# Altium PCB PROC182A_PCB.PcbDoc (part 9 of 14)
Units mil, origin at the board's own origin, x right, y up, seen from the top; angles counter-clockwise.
Board outline 3168.31 x 3700.79 mil, 8 copper layers (Top Layer, L2_GND1, L3_SIG1, L4_PWR1, L5_PWR2, L6_SIG2, L7_GND2, Bottom Layer), stack 58.1 mil thick; 580 components, 391 nets, 8314 pads, 4370 vias.
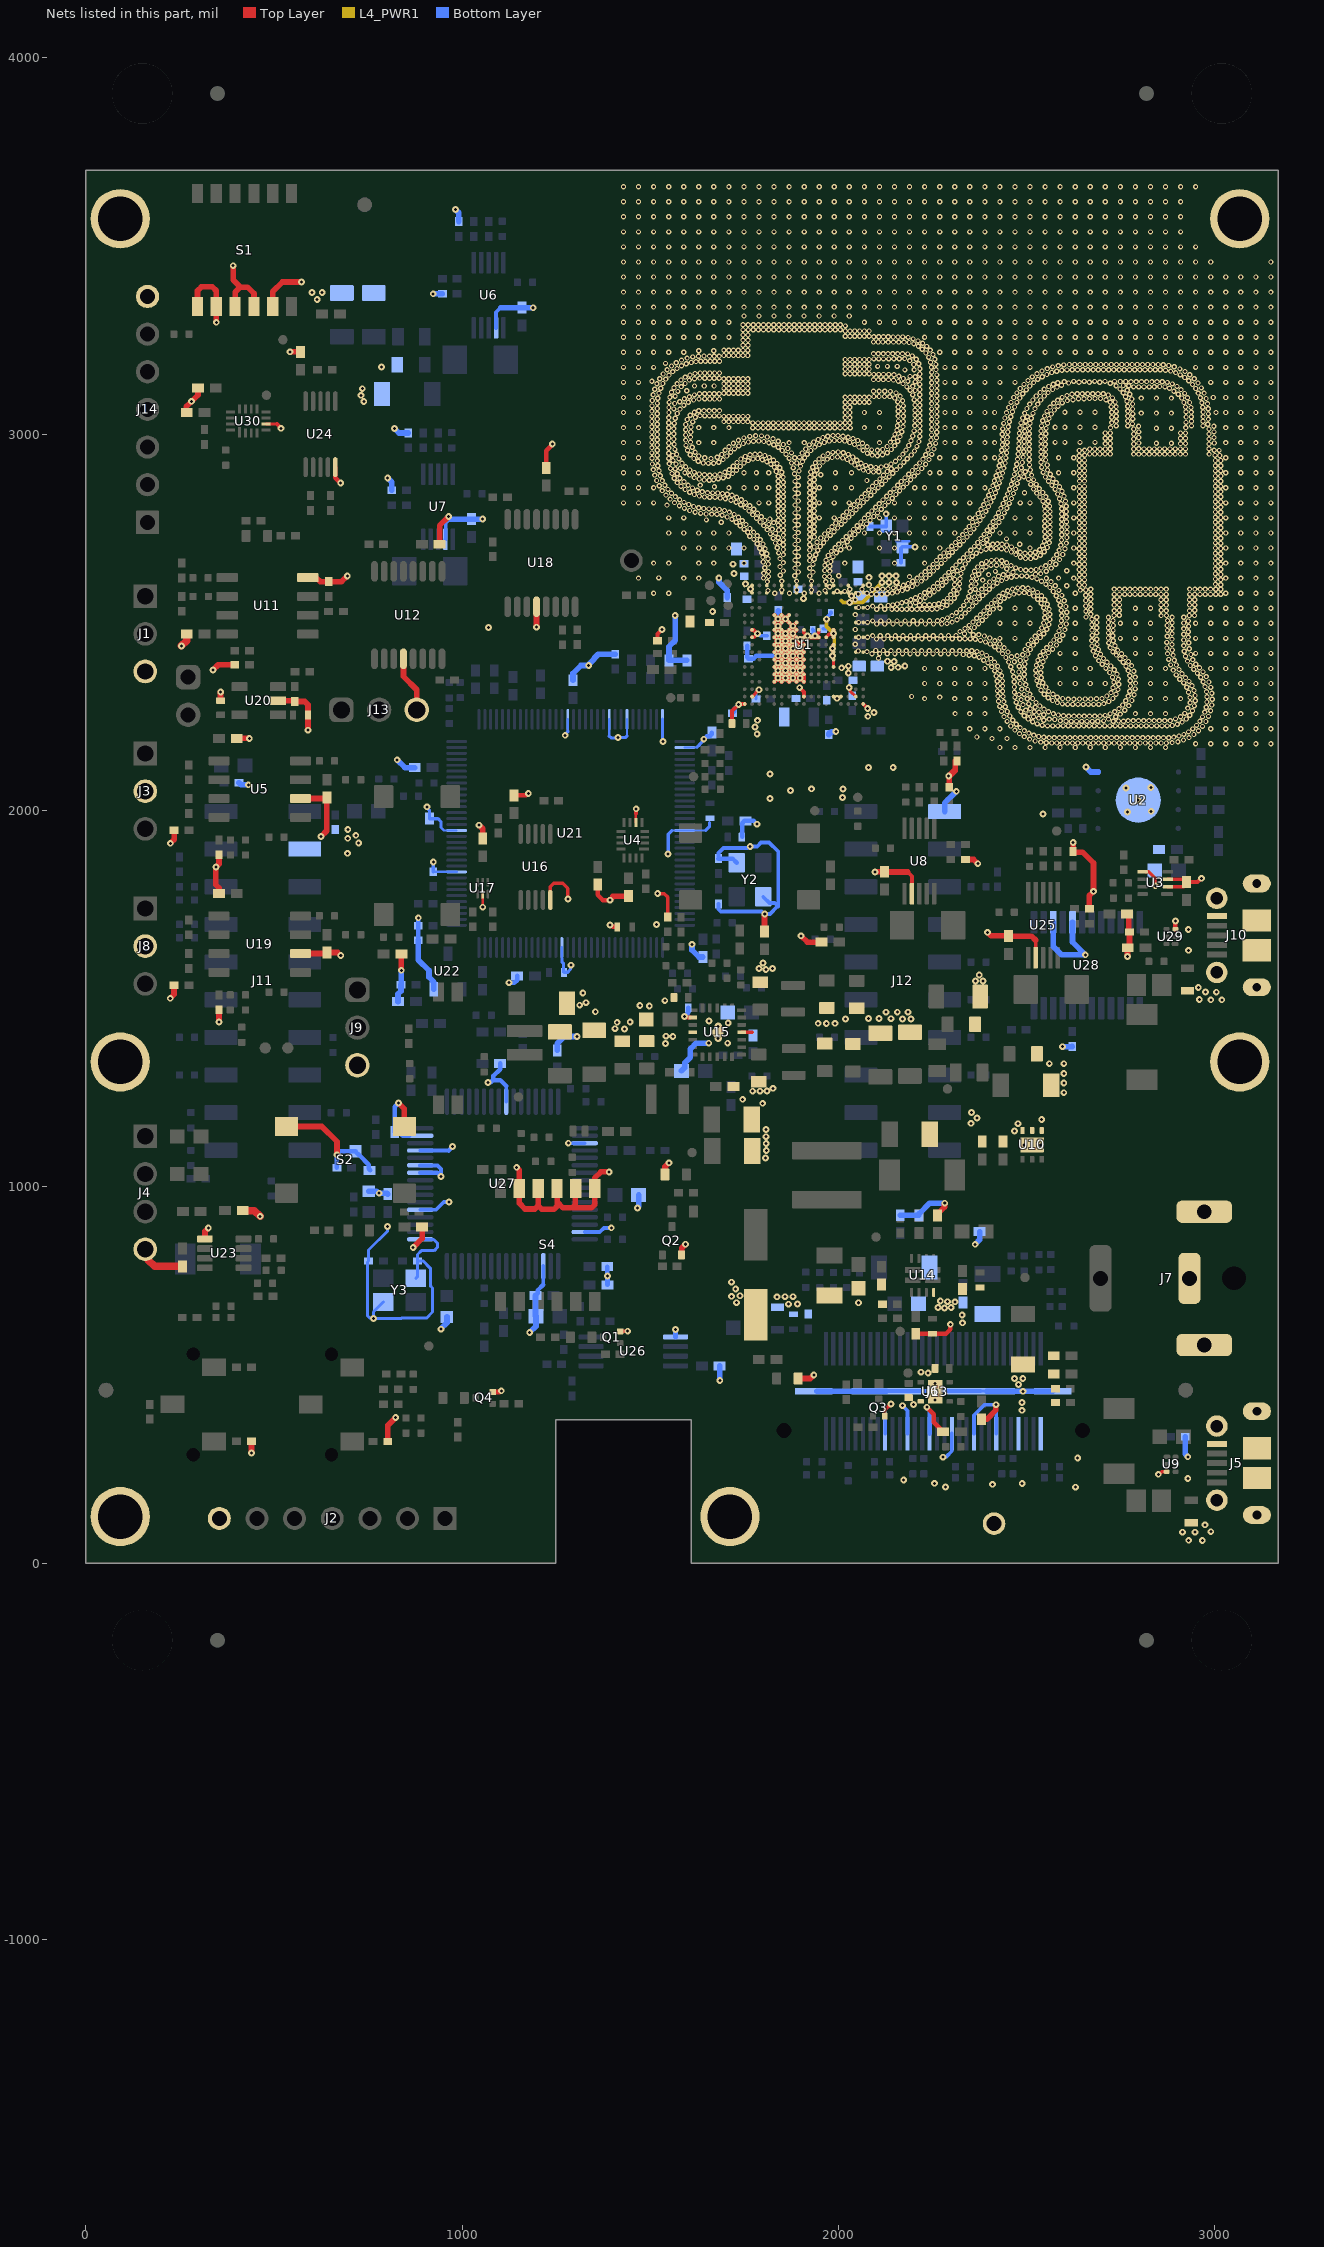
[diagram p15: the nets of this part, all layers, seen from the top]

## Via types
v1: diameter 13.77, hole 7, Top Layer to L2_GND1, tented both sides, 3444 vias
v2: diameter 18, hole 8, Top Layer to Bottom Layer, tented both sides, 911 vias
v3: diameter 13.77, hole 7, Top Layer to L2_GND1, tented top, 9 vias
v4: diameter 19.68, hole 7.87, Top Layer to Bottom Layer, 4 vias
v5: diameter 19.68, hole 7.87, Top Layer to Bottom Layer, tented both sides, 2 vias

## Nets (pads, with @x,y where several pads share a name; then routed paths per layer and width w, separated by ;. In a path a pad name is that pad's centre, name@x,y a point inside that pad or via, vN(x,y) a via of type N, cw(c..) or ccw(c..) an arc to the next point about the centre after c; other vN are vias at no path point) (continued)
GND: (continued)
  other v1: 2428.72,2167.48 2468.72,2167.48 2508.72,2167.48 2548.72,2167.48 2588.72,2167.48 2628.72,2167.48 2668.72,2167.48 2708.72,2167.48 2748.72,2167.48 2788.72,2167.48 2828.72,2167.48 2868.72,2167.48 2948.72,2177.48 2988.72,2177.48 3028.72,2177.48 3068.72,2177.48 3108.72,2177.48 3148.72,2177.48 2551.97,2180.12 2566.26,2179.62 2580.08,2179.62 2593.9,2179.62 2607.72,2179.62 2621.54,2179.62 2635.36,2179.62 2649.18,2179.62 2663,2179.62 2676.82,2179.62 2690.64,2179.62 2704.46,2179.62 2718.28,2179.62 2732.1,2179.62 2745.92,2179.62 2759.74,2179.62 2773.56,2179.62 2787.38,2179.62 2801.32,2179.62 2815.25,2179.62 2829.18,2179.62 2843.11,2179.64 2857.04,2179.64 2870.98,2179.64 2886.32,2180.47 2537.12,2181.81 2901.51,2182.99 2522.31,2184.91 2916.58,2187.38 2507.69,2189.76 2407.56,2191.44 2447.56,2191.44 2559.35,2193.71 2573.17,2193.71 2586.99,2193.71 2600.81,2193.71 2614.63,2193.71 2628.45,2193.71 2642.27,2193.71 2656.09,2193.71 2669.91,2193.71 2683.73,2193.71 2697.55,2193.71 2711.37,2193.71 2725.19,2193.71 2739.01,2193.71 2752.83,2193.71 2766.65,2193.71 2780.47,2193.71 2794.29,2193.71 2808.11,2193.71 2821.93,2193.71 2835.75,2193.71 2849.57,2193.71 2863.39,2193.71 2877.21,2193.68 2931.1,2193.82 2545.57,2194.68 2890.97,2195.03 2367.56,2195.44 2493.63,2196.46 2531.93,2196.91 2904.45,2198.05 2518.57,2200.44 2944.18,2202.11 2917.55,2202.48 2480.6,2204.52 2505.8,2205.73 2929.74,2208.99 2956.22,2212.02 2493.75,2212.5 2468.55,2213.85 2940.92,2217.1 2348.72,2217.48 2388.72,2217.48 2428.72,2217.48 2988.72,2217.48 3028.72,2217.48 3068.72,2217.48 3108.72,2217.48 3148.72,2217.48 2482.41,2220.4 2967.08,2223.62 2457.51,2224.73 2555.16,2224.97 2568.98,2224.96 2582.8,2224.96 2596.62,2224.96 2610.44,2224.96 2624.26,2224.96 2638.08,2224.96 2651.9,2224.96 2665.72,2224.96 2679.54,2224.96 2693.36,2224.96 2707.18,2224.96 2721,2224.96 2734.82,2224.96 2748.64,2224.96 2762.46,2224.96 2776.28,2224.96 2790.1,2224.96 2803.92,2224.96 2817.74,2224.96 2831.56,2224.96 2845.38,2224.96 2859.2,2224.96 2873.02,2224.96 2886.81,2225.83 2541.4,2226.33 2951.19,2226.35 2900.21,2229.22 2471.99,2229.48 2528.12,2230.15 2912.71,2235.1 2515.5,2235.78 2447.85,2236.85 2604.26,2237.28 2618.49,2236.86 2632.31,2236.86 2646.13,2236.86 2659.95,2236.86 2673.91,2236.86 2688.53,2237.05 2959.96,2237.03 2975.95,2236.43 2704.17,2238.27 2729.77,2237.36 2743.75,2237.92 2757.02,2237.38 2589.47,2238.82 2769.37,2239.05 2783.19,2239.05 2797.01,2239.05 2810.83,2239.05 2824.65,2239.05 2838.47,2239.05 2852.29,2239.05 2866.63,2238.91 2881.42,2238.98 2462.89,2239.88 2545.21,2239.76 2574.57,2241.85 2503.79,2243.11 2559.74,2242.87 2717.35,2242.9 2923.86,2243.27 2895.05,2243.54 2532.06,2245.61 2908.61,2249.22 2967.02,2248.91 2439.65,2249.68 2517.98,2249.41 2736.44,2249.35 2983.05,2250.21 2454.95,2251.19 2611.58,2250.95 2625.4,2250.95 2639.22,2250.95 2653.04,2250.95 2666.86,2250.95 2680.68,2250.95 2694.49,2251.23 2493.2,2251.99 2597.78,2251.78 2708.22,2252.8 2584.12,2253.86 2933.24,2253.42 2545.05,2254.39 2748.49,2256.16 2506.16,2256.88 2721.47,2256.75 2309.72,2257.48 2348.72,2257.48 2388.72,2257.48 2570.76,2257.4 2788.72,2257.48 2828.72,2257.48 2868.72,2257.48 2919.86,2258.14 3028.72,2257.48 3068.72,2257.48 3108.72,2257.48 3148.72,2257.48 2532.72,2261.08 2972.79,2261.47 2448.14,2263.21 2484.43,2262.68 2519.52,2262.48 2557.99,2262.69 2733.84,2262.91 2432.85,2263.42 2940.5,2265.18 2988.53,2265.13 2497.22,2266.98 2760.62,2266.55 2546.03,2269.61 2509.05,2270.9 2745.09,2270.93 2927.72,2272.18 2522.25,2274.29 2477.35,2274.55 2976.8,2274.7 2442.85,2275.98 2428.17,2276.72 2534.89,2277.79 2945.39,2278.11 2770.99,2278.75 2754.95,2280.61 2991.72,2280.48 2490.01,2281.53 2608.51,2282.19 2622.33,2282.19 2636.15,2282.19 2649.97,2282.19 2663.79,2282.19 2677.61,2282.19 2691.43,2282.14 2594.73,2283.29 2505.52,2283.38 2705.09,2284.24 2933.97,2286.27 2472,2287.29 2524.69,2287.12 2581.36,2286.77 2978.58,2288.4 2439.26,2289.33 2717.83,2289.57 2425.12,2290.48 2763.18,2291.72 2947.7,2291.73 2568.7,2292.31 2779.34,2292.56 2485,2294.84 2610.24,2296.08 2625.24,2295.94 2640.25,2296.28 2655.26,2296.28 2670.27,2296.28 2992.8,2295.83 2501.52,2297.08 2685.28,2297.09 2228.72,2297.48 2308.72,2297.48 2348.72,2297.48 2388.72,2297.48 2515.72,2297.63 2595.23,2297.61 2699.88,2297.73 2728.91,2297.83 2828.72,2297.48 2868.72,2297.48 2908.72,2297.48 3028.72,2297.48 3068.72,2297.48 3108.72,2297.48 3148.72,2297.48 2557.06,2299.78 2468.46,2300.65 2580.98,2300.99 2933.85,2300.42 2268.72,2301.48 2978.91,2302.22 2194.07,2303.05 2436.98,2302.96 2423.32,2303.98 2769.51,2304.01 2712.93,2304.33 2947.37,2305.55 2785.26,2307.63 2479.61,2308.45 2493.01,2308.64 2546.75,2308.97 2569.71,2309.19 2737.16,2308.92 2508.33,2309.31 2992.01,2311.72 2723.76,2313.47 2467.1,2314.4 2929.92,2314.36 2977.55,2315.97 2435.99,2316.74 2558.23,2316.68 2773.58,2317.21 2422.12,2317.88 2944.41,2319.04 2538,2319.67 2502.24,2321.71 2742.49,2321.67 2486.94,2322.71 2788.5,2323.22 2729.08,2326.46 2988.96,2327.19 2467.24,2328.22 2550.7,2328.13 2925.12,2327.57 2973.76,2329.26 2422.58,2330.9 2435.99,2330.56 2775.34,2330.92 2531.49,2331.86 2938.91,2331.72 2497.53,2334.71 2744.57,2335.34 2228.72,2337.48 2268.72,2337.48 2308.72,2337.48 2348.72,2337.48 2388.72,2337.48 2482.48,2337.44 2588.72,2337.48 2628.72,2337.48 2668.72,2337.48 2708.72,2337.48 2828.72,2337.48 2868.72,2337.48 3028.72,2337.48 3068.72,2337.48 3108.72,2337.48 3148.72,2337.48 2789.34,2338.67 2542.62,2339.68 2917.17,2339.31 2731.43,2340.79 2466.82,2342.03 2968.59,2342.08 2983.88,2341.71 2931.09,2343.12 2421.43,2343.78 2435.48,2344.37 2526.99,2344.93 2775.25,2344.74 2494.41,2348.17 2743.62,2349.12 2906.63,2348.89 2479.91,2352.83 2538.45,2352.96 2921.62,2353.18 2727.87,2354.26 2961.91,2354.18 2788.21,2354.44 2465.59,2355.8 2976.93,2355.92 2419.02,2357.58 2433.27,2358.01 2524.6,2358.54 2773.69,2358.47 2897.44,2360.36 2493.17,2361.93 2739.81,2362.41 2912.49,2363.56 2953.31,2364.99 2537.02,2366.59 2720.24,2366.89 2479.16,2368.26 2462.41,2369.25 2968.42,2368.54 2784.72,2370.3 2414.93,2371.13 2429.1,2371.19 2769.68,2371.7 2524.08,2372.35 2889.13,2373.12 2732.51,2374.14 2904.38,2374.75 2943.89,2375.1 2493.27,2375.75 2228.72,2377.48 2268.72,2377.48 2308.72,2377.48 2348.72,2377.48 2388.72,2377.48 2588.72,2377.48 2628.72,2377.48 2668.72,2377.48 2710.37,2377.81 2828.72,2377.48 2868.72,2377.48 2988.72,2377.48 3028.72,2377.48 3068.72,2377.48 3108.72,2377.48 3148.72,2377.48 2959.11,2379.35 2538.86,2381.04 2457.75,2382.26 2407,2382.44 2422.58,2383.38 2479.99,2383.45 2723.07,2384.24 2763.71,2383.51 2778.57,2385.17 2525.63,2386.08 2934.72,2385.45 2882.25,2386.94 2897.52,2386.75 2700.76,2388.73 2948.92,2388.78 2494.8,2389.49 2397.26,2392.34 2713.3,2394.01 2756.65,2393.75 2414.24,2394.39 2451.81,2394.74 2467.13,2395.25 2543.12,2395.48 2770.34,2395.94 2927.28,2397.09 2482.56,2398.63 2691.02,2398.37 2385.42,2399.43 2529.64,2399.31 2892.24,2399.52 2941.07,2401.09 2877.17,2401.74 2498.03,2402.93 2404.38,2404.07 2703.89,2404.13 2747.67,2403.38 2106.34,2404.56 2373.53,2406.98 2444.51,2406.47 2761.24,2406.39 2549.62,2407.99 2459.55,2408.84 2921.76,2409.76 2474.39,2411.22 2682.54,2411.09 2360.33,2411.38 2393.21,2412.22 2535.85,2411.66 2346.85,2412.74 2738.22,2412.88 2888.77,2412.89 2489.08,2414.18 2331.38,2414.6 2936.01,2414.61 2149.65,2416.28 2169.95,2416.28 2190.25,2416.28 2210.55,2416.28 2230.85,2416.28 2251.15,2416.28 2271.46,2416.28 2291.76,2416.28 2312.06,2416.28 2503.1,2415.78 2695.88,2415.4 2088.74,2416.56 2109.04,2416.81 2129.34,2416.47 2435.66,2417.08 2751.92,2416.43 2873.98,2416.94 2588.72,2417.48 2628.72,2417.48 2788.72,2417.48 2828.72,2417.48 2948.72,2417.48 2988.72,2417.48 3028.72,2417.48 3068.72,2417.48 3108.72,2417.48 3148.72,2417.48 2380.98,2418.66 2557.82,2419.68 2075.75,2422.25 2450.39,2421.36 2728.92,2422.08 2367.76,2422.67 2543.92,2422.88 2918.31,2423.15 2052.25,2423.95 2676.5,2423.62 2119.19,2425.22 2139.49,2424.94 2159.8,2424.9 2180.1,2424.9 2200.4,2424.9 2220.7,2424.9 2241,2424.9 2261.31,2424.9 2281.61,2424.9 2301.91,2424.9 2322.21,2424.9 2340.26,2425.02 2354.08,2424.63 2098.89,2425.39 2425.72,2426.68 2741.42,2426.38 2886.77,2426.57 2495.7,2427.91 2509.54,2428.01 2690.16,2427.98 2568.79,2428.39 2931.79,2430.01 2872.37,2432.04 2439.94,2432.49 2553.36,2432.97 2721.47,2432.95 2414.86,2435.23 2673.48,2437.23 2734.62,2438.08 2917.22,2438.21 2517.26,2439.47 2579.05,2439.74 2504.19,2441.27 2885.98,2441.06 2044.53,2441.72 2686.95,2441.42 2403.07,2442.45 2428.33,2442.5 2563.25,2442.62 2717.42,2445.48 2930.38,2445.78 2871.9,2446.87 2390.4,2447.95 2526.28,2449.94 2729.82,2451.08 2377.23,2452.15 2415.45,2451.31 2587.96,2452.23 2672.81,2451.55 2512.49,2453.13 2572.02,2453.3 2917.22,2453.27 2363.71,2455 2685.98,2455.21 2100.71,2455.89 2120.84,2456.06 2336.11,2456.26 2349.93,2456.09 2885.98,2455.55 2140.98,2456.34 2161.12,2456.38 2181.25,2456.38 2201.39,2456.38 2221.53,2456.38 2241.66,2456.38 2261.8,2456.38 2281.94,2456.38 2302.07,2456.38 2322.21,2456.38 2428.72,2457.48 2468.72,2457.48 2628.72,2457.48 2748.72,2457.48 2788.72,2457.48 2828.72,2457.48 2948.72,2457.48 2988.72,2457.48 3028.72,2457.48 3068.72,2457.48 3108.72,2457.48 3148.72,2457.48 2401.68,2458.38 2716.92,2458.48 2536.03,2459.74 2053.28,2460.58 2077.08,2460.59 2929.4,2460.85 2873.32,2463.28 2387.41,2463.66 2522.55,2463.42 2090.64,2464.72 2110.78,2464.47 2130.91,2464.81 2151.05,2464.5 2171.19,2464.5 2191.32,2464.5 2211.46,2464.5 2231.6,2464.5 2251.73,2464.5 2271.87,2464.5 2292.01,2465 2312.14,2465 2579.38,2465 2728.47,2464.63 2595.52,2465.96 2674.02,2465.48 2357.77,2466.9 2372.47,2467.49 2916.96,2468.33 2334.52,2469.88 2545.44,2469.86 2886.24,2470.04 2686.24,2472.08 2716.96,2472.08 2532.6,2473.05 2929.5,2475.16 2322.72,2475.88 2348.9,2477.88 2585.59,2477.34 2673.52,2479.28 2729.5,2478.55 2873.71,2478.55 2044.53,2481.09 2601.28,2480.68 2552.96,2481.45 2335.88,2483.58 2916.96,2483.39 2539.7,2485.09 2886.24,2484.53 2360.87,2486.3 2686.24,2485.89 2716.96,2485.89 2930.16,2489.47 2589.6,2490.57 2346.93,2491.88 2730.16,2491.73 2873.04,2491.73 2558.26,2494.22 2673.04,2493.69 2101.42,2495.54 2122.98,2495.54 2144.53,2495.54 2166.09,2495.54 2187.65,2495.54 2209.21,2495.54 2230.76,2495.54 2252.32,2495.54 2273.88,2495.54 2372.08,2496.02 2604.77,2495.58 2288.12,2496.98 2428.72,2497.48 2468.72,2497.48 2508.72,2497.48 2544.76,2498.28 2628.72,2497.48 2748.72,2497.48 2788.72,2497.48 2828.72,2497.48 2948.72,2497.48 2988.72,2497.48 3028.72,2497.48 3068.72,2497.48 3108.72,2497.48 3148.72,2497.48 2886.24,2499.02 2916.96,2498.45 2053.28,2499.95 2077.08,2499.96 2686.24,2499.7 2716.96,2499.7 2301.76,2500.7 2357.23,2501.1 2090.64,2503.84 2112.2,2503.84 2133.75,2503.84 2155.31,2503.84 2176.87,2503.84 2198.43,2504.05 2219.98,2503.8 2241.54,2504.12 2263.1,2504.16 2592.01,2504.18 2929.22,2503.77 2729.22,2504.9 2873.98,2504.9 2381.85,2505.79 2314.64,2506.73 2276.1,2507.75 2561.16,2507.73 2673.53,2508.1 2367,2510.87 2606.6,2511.19 2289.12,2511.83 2547.77,2512.18 2686.24,2513.51 2716.96,2513.51 2886.24,2513.51 2916.96,2513.51 2326.32,2514.78 2657.29,2514.4 2391.62,2515.57 2301.51,2517.86 2593.12,2517.95 2731.92,2518.08 2856.91,2517.94 2871.29,2518.08 2931.92,2518.08 2945.83,2518.05 2745.62,2519.02 2044.53,2520.46 2376.77,2520.64 2561.56,2521.54 2670.26,2521.81 2336.62,2524.48 2313.03,2525.5 2401.39,2525.34 2548.35,2525.56 2606.35,2526.99 2657.23,2529.46 2386.54,2530.42 2732.57,2531.23 2870.64,2531.23 2932.57,2531.23 2591.77,2531.7 2746.22,2532.33 2856.98,2532.33 2946.22,2532.33 2346.52,2534.08 2101.42,2534.91 2122.98,2534.91 2141.63,2534.91 2154.97,2534.91 2168.31,2534.91 2181.64,2534.91 2194.98,2534.91 2208.32,2534.91 2221.66,2534.91 2234.99,2534.91 2248.33,2534.91 2323.65,2534.35 2411.17,2535.11 2559.46,2535.2 2670.26,2535.12 2261.67,2536.38 2428.72,2537.48 2468.72,2537.48 2508.72,2537.48 2628.72,2537.48 2788.72,2537.48 2828.72,2537.48 2988.72,2537.48 3028.72,2537.48 3068.72,2537.48 3108.72,2537.48 3148.72,2537.48 2544.96,2538.75 2053.28,2539.32 2077.08,2539.33 2275,2539.55 2396.32,2540.19 2603.92,2542.08 2090.64,2543.21 2112.2,2543.21 2356.02,2543.58 2656.96,2543.42 2132.15,2544.81 2332.47,2544.98 2588.87,2545.22 2190.32,2546.08 2215.02,2545.68 2287.45,2545.56 2419.42,2546.28 2732.51,2546.2 2870.69,2546.2 2932.51,2546.2 2144.19,2546.52 2228.42,2546.68 2241.52,2546.98 2254.12,2547.28 2746.38,2546.36 2856.83,2546.36 2946.38,2546.36 2554.92,2548.26 2156.22,2548.88 2266.22,2549.28 2670.26,2548.44 2406.09,2549.96 2538.14,2550.78 2168.25,2551.89 2204.62,2551.88 2365.08,2552.99 2298.55,2553.79 2278.62,2555.18 2180.28,2555.63 2429.5,2555.8 2339.99,2556.58 2352.08,2556.74 2599.7,2557.24 2217.19,2557.9 2656.58,2557.92 2584.66,2558.38 2044.53,2559.83 2192.31,2560.07 2415.86,2559.73 2548.1,2560.28 2732.57,2560.12 2746.37,2560.12 2856.83,2560.12 2870.64,2560.12 2932.57,2560.12 2946.37,2560.12 2374.32,2562.25 2529.4,2561.35 2670.26,2561.75 2289.1,2563.6 2307.89,2563.98 2440.54,2564.09 2204.34,2565.16 2230.02,2564.98 2361.32,2567.38 2346.16,2568.94 2425.95,2569.18 2518.72,2569.88 2383.37,2571.22 2452.72,2570.58 2539.22,2570.87 2578.2,2570.59 2216.77,2571.37 2593.48,2571.74 2656.63,2571.93 2242.32,2572.86 2100.99,2574.23 2298.12,2573.7 2732.57,2574.29 2746.37,2574.29 2760.17,2574.29 2773.97,2574.29 2787.77,2574.29 2801.58,2574.29 2815.38,2574.29 2829.18,2574.29 2842.98,2574.29 2856.78,2574.29 2870.59,2574.29 2087.77,2574.34 2115.15,2574.41 2465.96,2575.11 2670.26,2575.06 2932.6,2574.39 2946.51,2574.39 2960.42,2574.39 2974.32,2574.39 2988.23,2574.39 3002.14,2574.39 3015.24,2574.39 2052.25,2575.44 2129.19,2575.79 2315.05,2575.8 1830.42,2577.09 1869.79,2577.09 1909.16,2577.09 1948.53,2577.09 2075.75,2577.14 2371.65,2576.86 2506.67,2576.76 1508.72,2577.48 1548.72,2577.48 2142.62,2577.79 2437.08,2577.38 2479.47,2578.27 2628.72,2577.48 3028.72,2577.48 3068.72,2577.48 3108.72,2577.48 3148.72,2577.48 2229,2578.47 2493.22,2578.98 2391.82,2579.88 2528.54,2579.63 2156.22,2580.78 2253.92,2580.88 2016.23,2582.24 2350.17,2582.17 2570.43,2582.02 1996.58,2582.46 2449.25,2583.92 1812.64,2584.82 1964.13,2584.82 2169.63,2584.61 2585.51,2584.82 1849.27,2585.85 1888.64,2585.85 1928.01,2585.85 2305.88,2585.75 2516.38,2586.2 2642.52,2585.78 2656.63,2585.83 2089.42,2587.3 2240.93,2586.34 2029.75,2588.06 2062.26,2587.8 2103.47,2588.2 2363.14,2587.7 2400.85,2588.11 2732.57,2588.28 2746.37,2588.28 2760.18,2588.28 2773.98,2588.28 2787.79,2588.28 2801.59,2588.28 2815.4,2588.28 2829.2,2588.28 2843.01,2588.28 2856.81,2588.28 2870.62,2588.28 2932.73,2588.23 2946.62,2588.23 2960.5,2588.23 2974.39,2588.23 2988.27,2588.23 3002.16,2588.14 3015.24,2588.14 2117.52,2588.4 2265.23,2588.99 2319.73,2588.8 2380.26,2588.42 2462.22,2588.67 2670.26,2588.37 2131.57,2589.55 2182.76,2589.45 2503.24,2590.48 2145.62,2591.58 2475.74,2591.55 2489.54,2592.3 2159.85,2592.64 2561.5,2592.57 1976.5,2594.83 2252.26,2594.67 2195.92,2595.38 2352.3,2595.82 2410.61,2596.7 2575.87,2597.25 2606.54,2597.29 2275.58,2598.21 2390.79,2597.86 2172.24,2598.43 2308.24,2599.79 2639.58,2599.35 2653.59,2599.35 3015.24,2599.8 2208.74,2602.01 2364.92,2601.78 2550.91,2601.45 3001.17,2601.65 2321.75,2602.47 2184.95,2603.37 2262.95,2603.79 2421.2,2604.07 2285.93,2607.66 2401.47,2607.39 2564.63,2608.27 1810.94,2608.32 1965.83,2608.32 2539.4,2609.11 1849.29,2609.65 1888.66,2609.65 1928.03,2609.65 2197.06,2609.43 2220.22,2609.51 2353.36,2609.6 1984.22,2610.65 2433.22,2610.89 2273.17,2613.18 2383.01,2612.35 2639.73,2612.76 2653.59,2612.76 2308.98,2613.89 3015.24,2613.56 2322.81,2616.25 2366.92,2615.38 2412.85,2615.59 2445.99,2616.18 2527.13,2615.46 3001.17,2615.33 1468.72,2617.48 1522.55,2618.24 1588.72,2617.48 1628.72,2617.48 1800.74,2617.79 2208.86,2617.5 2231.72,2617.78 2295.42,2617.6 2552.3,2617.4 2584.72,2617.48 2624.72,2617.48 3028.72,2617.48 3068.72,2617.48 3108.72,2617.48 3148.72,2617.48 2459.29,2619.91 2513.97,2619.67 1814.07,2621.77 1962.56,2621.82 1975.96,2621.91 2188.72,2621.48 1923.37,2623.18 2282.87,2623.03 2355.86,2623.19 2425.13,2622.55 2472.87,2622.47 2500.43,2622.44 1883.85,2623.66 2000.7,2623.92 2486.65,2623.56 1845.06,2625.1 2219.96,2625.87 2242.42,2626.88 2305.32,2627.18 2398.84,2626.96 2437.43,2626.74 2639.88,2626.57 2653.59,2626.57 2372.52,2627.98 2523.27,2628.26 3015.24,2627.32 2450.17,2628.8 3001.17,2629 2325.42,2629.82 2536.84,2629.43 1801.14,2630.88 2292.64,2632.8 2463.67,2632.96 1893.02,2633.71 1932.28,2633.48 1814.12,2635.18 2230.62,2634.78 1976.82,2636.08 2361.38,2635.87 2416.64,2635.48 2551.62,2635.7 1853.38,2636.53 2252.43,2636.53 2315.12,2636.98 2606.54,2637.29 1963.07,2637.8 2380.82,2638.88 2497.41,2638.45 2511.22,2638.38 2483.74,2640.54 2524.91,2640.34 2639.72,2640.38 2653.59,2640.38 3015.24,2641.07 2302.41,2642.57 2329.92,2642.89 2447.07,2642.38 3001.17,2642.68 1884.33,2644.19 1923.16,2643.78 2565.07,2644.2 1803.92,2644.88 2241.15,2644.44 2470.58,2644.75 2538.09,2644.48 2262.68,2646.62 2369.61,2646.96 1844.66,2648.14 2391.62,2647.78 1977.02,2649.28 2434.1,2649.48 2405.02,2651.28 2458.32,2651.14 2550.38,2650.81 1963.67,2651.61 2419.56,2651.63 2312.18,2652.34 1932.28,2654.08 2251.34,2654.12 2639.72,2654.19 2653.59,2654.19 1813.58,2655.15 1893.02,2654.66 2336.43,2655.08 2577.02,2654.6 3015.24,2654.83 2380.28,2655.75 2272.72,2656.61 3001.17,2656.35 1508.72,2657.48 1548.72,2657.48 1628.72,2657.48 1668.72,2657.48 1748.72,2657.48 2016.32,2657.48 2148.72,2657.48 2228.72,2657.48 2624.72,2657.48 3028.72,2657.48 3068.72,2657.48 3108.72,2657.48 3148.72,2657.48 1853.38,2658.66 2446.56,2658.38 2561.52,2658.98 1800.2,2660.42 1979.72,2661.73 2321.96,2662.12 2392.76,2661.69 2433.72,2663.51 1884.33,2665.14 1923.16,2664.38 1966.77,2665.07 2260.29,2664.56 2406.26,2664.66 2345,2665.92 2420.05,2665.51 2282.71,2666.76 2587.38,2666.73 1935.51,2667.88 2639.83,2668 2653.59,2668 1812.49,2668.93 2571.35,2668.7 3015.24,2668.59 1844.66,2669.32 2496.61,2669.73 2510.43,2669.51 3001.17,2670.03 2331.73,2671.89 2483.22,2673.15 2523.92,2672.49 1799.12,2673.38 1985.32,2673.88 2270.06,2674.33 1893.02,2675.61 2355.01,2675.45 2292.6,2676.85 1923.33,2677.91 1972.69,2677.56 2536.35,2678.53 1853.54,2679.9 1939.4,2679.83 2471.17,2679.92 2579.65,2679.75 2595.8,2680.46 2341.5,2681.66 2639.58,2681.81 2653.59,2681.81 1809.36,2682.39 2509.18,2683.22 3015.24,2682.35 2279.83,2684.11 2366.26,2683.47 2495.5,2683.61 3001.17,2683.7 1796.1,2684.81 1840.82,2684.68 1994.22,2685.01 1884.33,2686.09 2522.62,2686.18 2302.44,2686.38 2459.2,2686.83 2482.52,2686.58 2546.74,2687.65 1981.14,2688.5 2378.55,2689.8 1944.69,2691.26 1923.7,2692.25 2351.32,2691.68 2446.43,2692.1 2586.05,2691.99 2005.82,2693.14 2290.92,2692.55 2534.24,2692.85 1853.54,2693.48 2391.77,2693.84 2471.14,2693.67 1804.92,2695.47 2405.45,2695.78 2433.02,2695.44 2601.83,2695.35 2639.75,2695.62 2653.59,2695.62 3015.24,2696.1 1790.81,2696.67 1893.02,2696.56 2311.92,2696.48 2419.25,2696.58 1588.72,2697.48 1628.72,2697.48 1668.72,2697.48 1708.72,2697.48 1748.72,2697.48 1837.12,2698.08 1990.97,2698.22 2028.72,2697.48 2108.72,2697.48 2148.72,2697.48 2228.72,2697.48 2268.72,2697.48 2508.72,2697.48 2624.72,2697.48 3001.17,2697.38 3028.72,2697.48 3068.72,2697.48 3108.72,2697.48 3148.72,2697.48 2554.7,2698.95 1935.1,2700.09 2372.79,2700.53 2459.42,2700.48 1951.65,2701.65 2300.51,2702.21 2360.83,2701.9 2015.59,2702.91 2541.97,2703.71 2590.27,2705.16 1853.36,2706.24 1923.7,2706.07 2322.28,2706.27 2396.62,2706.28 2446.7,2705.48 1884.33,2707.04 1799.19,2708.05 2000.74,2707.99 2409.74,2707.98 2434.28,2707.88 2481.28,2707.32 1783.92,2708.68 2421.96,2709.1 2383.91,2709.77 2639.94,2709.43 2653.59,2709.43 3015.24,2709.86 1832.22,2710.68 2605.33,2710.57 3001.17,2711.05 1843.08,2712.27 1960.35,2711.73 2310.75,2712.23 2559.83,2711.78 1942.67,2712.66 2369.95,2712.32 2023.32,2713.88 2546.91,2715.16 2331.96,2716.41 1893.02,2717.51 2010.51,2717.76 1853.54,2719.01 2592.39,2718.81 1791.97,2719.84 1923.7,2719.89 2393.82,2719.66 1775.04,2720.49 1968.29,2721.43 2446.39,2721.69 1826.12,2722.98 2033.42,2723.28 2320.12,2722.77 2378.44,2722.76 2639.8,2723.24 2653.59,2723.24 1952.98,2724.27 3015.24,2723.62 1839.97,2725 3001.17,2724.72 2561.84,2725.45 2606.79,2725.39 1935.59,2726.8 2341.34,2726.91 1884.33,2727.99 2020.28,2727.53 2549.11,2727.35 1764.26,2728.98 1784.05,2730.38 1978.07,2731.13 1853.54,2731.77 2400.93,2731.69 2043.32,2733.28 2329.55,2733.17 2593.03,2732.62 1923.7,2733.71 2386.85,2733.72 1819.02,2735.08 1963.2,2734.57 1832.46,2736.26 2640.04,2737.05 2653.59,2737.05 1548.72,2737.48 1588.72,2737.48 1628.72,2737.48 1668.72,2737.48 1708.72,2737.48 2030.05,2737.3 2068.72,2737.48 2108.72,2737.48 2148.72,2737.48 2188.72,2737.48 2228.72,2737.48 2268.72,2737.48 2308.72,2737.48 2350.47,2737.72 2428.72,2737.48 2468.72,2737.48 2508.72,2737.48 2624.72,2737.48 3015.24,2737.38 3028.72,2737.48 3068.72,2737.48 3108.72,2737.48 3148.72,2737.48 1893.02,2738.46 2561.79,2739.27 3001.17,2738.4 1758.5,2739.4 1774.48,2739.68 2607.12,2739.53 1935.59,2740.62 1987.84,2740.83 2547.92,2741.38 2409.44,2743.24 2053.02,2743.38 2338.77,2743.64 1853.54,2744.53 1972.99,2744.35 2395.26,2744.69 1810.52,2746.28 1841.22,2745.48 1749.29,2747.1 2039.83,2747.08 2593.03,2746.44 1824.12,2747.68 1923.7,2747.53 1884.33,2748.94 2359.49,2748.43 1764.47,2749.51 1997.61,2750.54 2639.91,2750.86 2653.59,2750.86 3015.24,2751.13 3001.17,2752.07 2063.22,2752.98 2561.79,2753.09 1982.76,2754.13 2607.12,2753.42 1935.59,2754.44 2347.32,2754.55 2417.37,2755.28 2547.92,2755.23 2403.17,2756.02 1739.02,2756.64 1801.5,2756.99 1853.54,2757.29 2049.6,2756.85 1840.22,2758.18 1754.17,2760.11 1815.02,2760.18 1893.02,2759.41 2007.38,2760.24 2368.01,2759.69 2593.03,2760.26 1923.7,2761.35 2074.22,2761.54 1992.53,2763.9 1828,2764.91 2639.82,2764.67 2653.59,2764.67 3015.24,2764.89 1728.44,2766.11 2355.8,2765.68 2426.32,2766.14 3001.17,2765.75 1791.72,2766.76 2059.37,2766.62 2561.79,2766.91 2605.52,2767.08 1935.59,2768.26 2410.6,2767.68 2547.92,2769.05 1744.4,2769.88 1853.54,2770.06 1884.33,2769.89 2017.16,2769.94 1804.42,2770.68 2375.86,2771.16 1840.02,2771.68 2083.99,2771.32 1716.73,2774.02 2002.31,2773.67 2592.98,2774.11 1817.62,2774.48 1923.7,2775.17 1781.94,2776.53 2069.14,2776.39 1548.72,2777.48 1588.72,2777.48 1948.72,2777.48 1988.72,2777.48 2108.72,2777.48 2148.72,2777.48 2188.72,2777.48 2228.72,2777.48 2268.72,2777.48 2308.72,2777.48 2348.72,2777.48 2363.46,2777.33 2468.72,2777.48 2508.72,2777.48 2624.72,2777.48 3028.72,2777.48 3068.72,2777.48 3108.72,2777.48 3148.72,2777.48 1734.08,2779.07 2433.85,2778.45 2639.56,2778.48 2653.59,2778.48 3015.24,2778.65 1703.94,2780.06 2026.93,2779.64 2418.02,2779.33 3001.17,2779.42 1794.62,2780.48 1893.02,2780.36 2093.77,2781.09 2561.79,2780.73 2604.82,2780.88 1935.59,2782.08 2548.11,2782.28 1853.54,2782.82 2384.12,2782.84 2012.08,2783.44 1690.65,2784.32 1840.34,2785.06 1772.17,2786.3 2078.92,2786.17 1676.96,2786.98 1722.59,2786.75 1648.33,2787.83 1662.95,2787.51 2592.99,2787.98 1923.7,2788.99 2371.13,2789.05 1633.6,2789.61 1784.62,2790.18 2036.7,2789.34 1884.33,2790.84 2103.54,2790.86 2425.05,2791.23 2440.73,2790.86 2639.8,2792.29 2653.59,2792.29 1618.98,2792.53 1710.15,2792.77 2021.85,2793.21 3001.17,2793.1 3015.24,2792.41 2391.46,2795.28 2561.79,2794.55 2605.01,2794.63 1762.21,2795.88 1840.02,2795.39 1853.54,2795.58 1935.59,2795.9 2088.69,2795.94 2548.42,2795.58 1604.42,2797.04 1697,2797.03 2046.47,2799.04 1683.5,2799.99 1774.72,2800.28 1669.73,2801.08 2113.31,2800.63 2378.43,2800.7 1655.91,2801.36 1893.02,2801.31 2592.99,2801.71 1590.44,2802.8 1642.13,2802.44 1923.7,2802.81 2031.62,2802.99 2447.19,2803.26 2431.43,2803.49 1628.5,2804.72 1751.71,2804.86 2098.46,2805.71 2639.86,2806.1 2653.59,2806.1 3015.24,2806.16 3001.17,2806.77 1615.06,2807.94 2398.5,2807.49 1840.02,2808.61 1853.54,2808.35 2056.24,2808.74 2546.93,2808.63 2560.73,2808.33 2605.22,2808.48 1577.12,2809.8 1764.09,2810.11 1935.59,2809.72 2123.08,2810.4 1884.33,2811.79 1602.19,2812.97 1740.14,2812.42 2041.39,2812.76 2385.36,2812.86 2590.87,2815.23 2108.23,2815.48 2437.81,2815.75 2453.69,2816.14 1923.7,2816.63 1428.72,2817.48 1468.72,2817.48 1508.72,2817.48 1564.38,2818.2 1788.72,2817.48 1814.72,2817.48 1948.72,2817.48 1988.72,2817.48 2028.72,2817.48 2148.72,2817.48 2188.72,2817.48 2228.72,2817.48 2268.72,2817.48 2308.72,2817.48 2348.72,2817.48 2482.72,2817.48 2508.72,2817.48 2624.72,2817.48 3028.72,2817.48 3068.72,2817.48 3108.72,2817.48 3148.72,2817.48 1589.58,2818.62 1727.98,2819 1752.99,2818.49 2066.02,2818.45 2132.85,2820.18 2404.88,2819.75 2639.86,2819.91 2653.59,2819.91 3015.24,2819.92 1853.54,2821.11 3001.17,2820.45 1840.02,2821.83 1893.02,2822.26 2543.32,2821.72 2557.02,2821.64 2602.82,2822.21 2051.17,2822.53 1714.22,2824.18 1935.59,2823.54 2118,2825.25 2391.99,2825.02 1577.79,2825.85 1741.52,2826.08 1552.64,2827.4 1699.32,2828.18 2075.79,2828.15 2443.91,2828.15 2587.22,2828.28 2459.58,2829.15 2142.63,2829.95 1685.69,2830.47 1923.7,2830.45 1658.02,2832.08 1671.92,2831.98 2060.94,2832.3 2411.26,2832.01 1644.07,2833.05 1729.35,2832.48 1884.33,2832.74 2535.42,2832.98 1566.62,2833.97 1853.54,2833.87 2550.87,2834.02 2640.08,2833.72 2653.59,2833.72 3001.17,2834.12 3015.24,2833.68 1840.02,2835.05 2127.78,2835.03 1630.27,2835.73 2598.92,2835.48 1541.67,2837.99 1716.84,2837.59 1935.59,2837.36 2085.56,2837.85 2398.7,2837.48 1617.12,2839.78 2152.4,2839.72 1704.32,2840.48 2449.2,2840.92 2581.97,2841.08 1691.82,2842.28 2070.71,2842.08 2464.98,2842.24 1556.11,2842.95 1893.02,2843.21 1665.42,2843.88 1679.22,2843.58 1923.7,2844.27 2526.82,2843.38 1651.82,2844.68 2137.55,2844.8 2417.09,2844.54 2494.09,2844.45 2542.5,2845.02 1604.52,2845.48 1638.02,2847.28 1853.54,2846.63 1840.02,2848.26 2095.33,2847.55 2593.82,2848.28 2639.83,2847.53 2653.59,2847.53 3001.17,2847.8 3015.24,2847.44 1531.86,2849.97 2162.17,2849.49 1624.62,2851.18 1935.59,2851.18 2404.16,2850.31 2080.48,2851.85 1546.83,2853.19 1592.42,2852.98 2575.46,2853.16 1884.33,2853.69 2454.47,2853.69 2518.02,2854.28 2147.32,2854.57 2470.08,2855.49 2533.41,2855.43 1612.1,2857.19 2105.11,2857.25 1428.72,2857.48 1468.72,2857.48 1508.72,2857.48 1708.72,2857.48 1748.72,2857.48 1781.72,2857.48 1814.72,2857.48 1923.7,2858.09 1948.72,2857.48 1991.54,2857.48 2034.37,2857.48 2202.72,2857.48 2228.72,2857.48 2268.72,2857.48 2308.72,2857.48 2348.72,2857.48 2388.72,2857.48 2422.66,2857.61 2624.72,2857.48 3028.72,2857.48 3068.72,2857.48 3108.72,2857.48 3148.72,2857.48 2171.94,2859.27 1853.54,2859.4 2587.22,2860.48 3015.24,2861.19 1581.52,2861.58 1840.02,2861.48 2090.26,2861.62 2640.07,2861.34 2653.59,2861.34 3001.17,2861.47 1523.55,2862.97 2410.13,2863.21 1893.02,2864.16 1538.77,2864.42 1600.36,2864.47 1935.59,2865 2157.09,2864.34 2566.75,2864.42 2114.88,2866.95 2459.13,2866.7 2510.51,2866.54 2525.23,2866.57 2181.72,2869.04 2474.89,2869.15 1571.32,2871.28 2427.45,2870.43 2578.52,2871.18 1853.54,2872.16 1923.7,2871.91 2100.03,2871.39 1589.42,2873.78 2166.87,2874.12 1840.02,2874.83 1884.33,2874.64 2557.67,2874.84 2640.12,2875.15 2653.59,2875.15 3001.17,2875.15 3015.24,2874.95 1516.78,2876.82 1532.11,2876.53 2075.27,2877.02 2124.65,2876.65 2414.18,2876.33 1642.85,2878.28 1656.53,2877.46 1668.02,2878.48 1935.59,2878.82 2191.49,2878.81 2518.31,2878.53 2463.71,2879.74 2504.65,2879.86 1629.52,2880.96 1680.34,2881.2 2109.8,2881.16 2569.62,2881.68 1563.62,2882.88 1578.42,2883.08 2432.05,2883.19 2479.08,2882.99 1693.79,2883.87 2176.64,2883.89 1616.41,2884.67 1893.02,2885.11 1852.87,2885.98 1924.04,2885.73 2549.62,2886.07 2134.42,2886.36 2492.45,2886.73 1706.88,2888.16 1840.02,2888.19 1526.82,2889.29 2201.26,2888.58 2640.12,2888.96 2653.59,2888.96 3001.17,2888.82 3015.24,2888.71 2419.2,2889.45 1511.61,2891.26 1604.3,2891.16 1657.62,2891.2 2119.57,2890.94 2513.02,2891.3 1643.82,2891.94 1671.44,2891.69 1936.96,2891.97 1952.57,2892.35 2467.12,2893.14 1630.19,2894.2 1685.07,2893.94 2186.41,2893.66 2562.66,2893.63 1571.32,2894.78 1718.54,2895.24 1883,2894.92 1557.62,2895.58 2144.19,2896.06 1591.76,2897.24 2435.94,2896.45 2482.52,2896.65 1428.72,2897.48 1468.72,2897.48 1748.72,2897.48 1781.72,2897.48 1814.72,2897.48 1991.54,2897.48 2034.37,2897.48 2242.72,2897.48 2268.72,2897.48 2308.72,2897.48 2348.72,2897.48 2388.72,2897.48 2584.72,2897.48 2624.72,2897.48 3028.72,2897.48 3068.72,2897.48 3108.72,2897.48 3148.72,2897.48 1617.03,2898.42 1698.05,2898.7 1849.49,2898.67 2211.15,2898.48 2543.44,2898.43 1926.39,2899.35 2092.98,2899.38 2495.88,2900.06 1834.32,2900.78 2079.26,2900.84 2106.65,2900.32 2129.34,2900.71 1895.15,2902.02 1522.95,2902.56 2423.62,2902.5 2640.34,2902.78 2653.59,2902.78 3001.17,2902.49 3015.24,2902.47 1729.02,2904.11 1942.05,2904.01 2196.18,2903.43 1604.83,2904.91 2066.04,2904.56 2509.48,2904.66 2555.24,2904.81 1507.79,2905.77 1709.9,2905.81 2153.97,2905.76 2470.48,2906.54 1566.25,2907.64 2140.26,2908.14 1553.46,2908.6 1579.93,2909.3 2221.22,2908.82 2439.3,2909.86 1843.62,2910.98 1879.87,2910.38 2054.21,2910.6 2485.79,2910.78 1829.52,2911.78 1931.3,2912.26 2099.3,2911.7 2539.43,2911.65 1593.81,2913.25 2085.56,2913.18 2113.1,2912.58 2205.95,2913.2 1738.72,2913.93 1720.39,2914.8 1898.92,2915.06 1519.9,2916.04 1949.42,2915.53 2126.58,2915.62 2163.74,2915.46 2426.79,2915.85 3001.17,2916.17 3015.24,2916.22 2072.28,2916.99 2639.86,2916.59 2653.59,2916.59 2043.48,2917.97 2554.4,2918.19 2507.41,2918.32 1820.22,2920.04 2231.29,2920.23 2473.39,2920.05 1505.46,2920.82 1568.06,2920.54 2139.41,2920.74 1550.32,2921.81 1836.52,2921.88 1584.1,2923.08 1654.26,2922.44 1668.08,2922.46 1748.83,2923.21 2059.8,2922.93 2215.48,2923.21 1640.48,2923.53 1875.22,2923.39 1889.02,2923.48 1938.58,2924.01 2442.48,2923.31 1730.16,2924.58 2173.51,2925.16 2488.34,2924.82 1681.57,2925.44 1958.72,2925.69 2033.67,2926.01 2537.92,2925.39 1809.72,2926.48 1904.33,2927.12 1627.42,2928.05 2151.29,2927.81 1518.82,2929.82 1560.22,2930.18 1760.25,2929.7 2429.52,2929.48 3001.17,2929.84 3015.24,2929.98 1827.37,2930.72 2048.39,2930.73 2639.67,2930.4 2653.59,2930.4 1797.75,2931.82 2506.59,2932.12 2550.12,2931.38 1693.48,2932.46 2022.69,2932.79 2240.35,2932.84 1575.89,2934.2 1740.52,2933.88 1772.89,2934.07 1947.96,2934.16 1969.94,2933.79 2224.36,2933.8 2475.41,2933.72 2182.56,2934.86 1504.52,2935.93 1549.18,2935.52 1615.74,2935.43 1661.12,2935.48 1785.23,2935.4 1868.71,2935.58 1644.52,2937.08 1883.77,2937.09 2010.74,2936.59 2161.9,2936.66 2444.5,2936.98 1428.72,2937.48 1468.72,2937.48 1816.32,2938.28 1909.82,2937.33 1983.03,2937.97 2268.72,2937.48 2308.72,2937.48 2348.72,2937.48 2388.72,2937.48 2414.72,2937.48 2584.72,2937.48 2624.72,2937.48 3028.72,2937.48 3068.72,2937.48 3108.72,2937.48 3148.72,2937.48 1677.62,2938.58 1896.33,2938.34 1997.3,2939.19 2490.42,2938.95 2537.83,2939.21 2037.61,2939.37 1752.02,2940.48 1628.64,2942.05 1703.44,2942.04 1959.11,2942.33 2103.3,2942.82 2639.67,2942.98 1518.34,2943.63 1559.22,2943.68 1804.31,2943.47 2089.55,2944.2 2431.51,2943.56 2653.68,2943.98 3000.17,2943.52 3013.02,2943.43 1606.05,2945.28 1764.77,2945.06 2116.92,2945.14 2192.98,2944.56 1689.62,2946.02 2025.59,2946.19 2231.72,2945.5 2247.69,2946.27 2506.59,2945.94 2550.12,2945.38 1569.87,2946.65 1778.12,2946.98 1791.24,2946.49 1860.31,2946.56 1917.01,2946.68 2171.01,2947.05 2667.11,2947.19 2680.76,2947.19 2694.41,2947.19 2708.07,2947.19 2721.72,2947.19 2783.9,2946.87 2797.71,2946.87 2811.51,2946.87 2825.31,2946.87 2839.11,2946.87 2852.91,2946.87 2866.72,2946.87 2880.52,2946.87 2894.32,2946.87 2908.12,2946.87 2921.92,2946.87 2984.48,2946.97 1971.61,2948.23 2477.44,2947.39 2076.64,2949.14 1504.26,2950.3 1549.1,2949.38 1875.17,2950.24 1903.31,2950.08 2012.49,2950.6 2129.58,2950.69 2446.53,2950.65 1618.93,2951.9 1713.21,2951.81 1985,2951.64 1998.79,2952.44 2537.83,2953.03 2492.07,2953.36 2201.69,2955.3 1598.87,2957.09 1698.6,2957.07 1850.72,2956.51 1926.51,2956.72 2065.29,2957.03 2103.35,2957.05 2433.82,2957.08 2639.67,2956.55 2997.72,2957.18 3011.02,2956.98 1518.34,2957.45 2087.99,2958.25 2179.42,2958.02 2237.73,2957.95 2653.68,2957.55 2117.07,2959.22 2140.47,2959.19 1565.33,2959.64 2506.59,2959.76 2550.1,2959.44 1723.6,2960.92 1912.88,2960.47 2253.55,2960.42 2478.57,2961.17 2667.41,2960.59 2681.06,2960.59 2694.71,2960.59 2708.37,2960.59 2721.72,2961.19 2784.32,2960.4 2811.51,2960.87 2825.32,2960.87 2839.12,2960.87 2852.93,2960.87 2866.73,2960.87 2880.54,2960.87 2894.34,2960.87 2908.15,2960.87 2921.95,2960.87 2984.17,2961.13 1864.98,2961.93 2797.71,2961.65 1549.11,2962.89 1504.25,2964.36 1839.92,2965.13 2447.64,2964.42 1611.36,2965.35 1937.19,2965.49 2054.51,2965.67 1708.98,2966.78 2075.83,2966.75 2129.15,2967.12 2537.83,2966.85 2208.2,2967.48 2492.98,2967.4 1734.95,2968.82 1594.74,2970.28 2149.49,2969.67 2186.64,2969.8 1518.34,2971.27 2242.42,2970.95 1827.83,2971.83 1922.26,2971.39 1949.24,2972.27 2435.22,2971.68 1563.23,2973.3 1853.13,2972.48 2042.44,2972.4 2549.49,2973.22 2506.59,2973.58 2784.32,2973.71 2984.32,2973.71 1747.23,2975.14 2479.25,2974.97 2708.37,2974.79 2721.72,2975.19 2908.37,2974.79 2921.72,2975.19 1720.61,2975.95 2063.83,2975.62 2257.89,2975.41 2844.38,2975.86 2884.38,2975.86 1549.11,2976.39 1814.99,2976.95 2798.01,2976.44 2998.01,2976.44 1428.72,2977.48 1468.72,2977.48 1504.25,2978.18 1628.72,2977.48 1668.72,2977.48 1868.72,2977.48 1908.72,2977.48 1961.92,2977.75 2029.73,2977.83 2108.72,2977.48 2282.72,2977.48 2308.72,2977.48 2348.72,2977.48 2388.72,2977.48 2414.72,2977.48 2448.32,2978.23 2575.47,2978.11 2601.47,2978.11 2641.47,2978.11 2681.47,2978.11 3028.72,2977.48 3068.72,2977.48 3108.72,2977.48 3148.72,2977.48 1606.85,2978.8 1760.44,2979.22 1934,2979.19 2137.85,2978.86 1801.65,2980.56 1839.9,2981.19 2157.18,2981.15 2213.39,2980.37 2493.22,2980.4 2537.83,2980.67 1774.09,2981.37 1787.9,2981.92 1975.18,2981.67 2016.46,2981.69 1988.91,2983.23 2002.73,2983.26 2051.27,2983 2192.42,2982.36 1593.83,2984.07 1733.84,2984.02 1518.34,2985.09 2245.62,2984.39 1945.92,2985.78 2436.42,2985.78 1562.58,2987.1 2549.77,2986.99 2784.32,2987.02 2984.32,2987.02 1825.86,2987.73 2145.98,2988.11 2506.59,2987.4 2038.61,2988.45 2479.89,2988.78 2708.37,2988.98 2721.72,2989.18 2908.37,2988.98 2921.72,2989.18 1549.11,2989.89 1748.53,2990.17 1958.56,2990.95 2260.29,2990.44 2797.63,2991.22 2997.63,2991.22 1504.25,2992 1606.62,2992.24 2025.57,2991.78 2448.68,2992.04 1810.86,2992.56 1764.09,2993.99 2163.42,2993.48 2215.91,2994.11 2493.42,2993.98 1795.19,2995.29 1971.51,2994.63 2011.98,2994.68 2197.37,2995.26 2537.83,2994.49 1779.62,2995.64 1985.14,2996.44 1998.59,2996.4 1593.83,2997.89 2246.85,2998.16 1518.34,2998.91 2149.79,2999.38 2435.06,2999.59 1562.58,3000.92 2506.59,3001.22 2550.38,3001.16 2784.32,3000.34 2984.32,3000.34 2480.49,3002.58 2708.37,3003.18 2721.72,3003.18 2908.37,3003.18 2921.72,3003.18 1549.11,3003.39 2261.14,3004.85 1504.25,3005.82 1607.47,3005.69 2449.59,3005.83 2797.36,3006 2997.36,3006 2168.13,3006.47 2216.24,3007.91 2494.29,3007.83 2200.6,3008.7 2201.62,3008.75 2537.92,3008.31 2155.26,3010.4 1593.83,3011.71 2247.26,3011.97 1518.34,3012.73 2436.35,3013.97 2784.32,3013.65 2984.32,3013.65 1562.58,3014.74 2507.3,3015.02 2551.42,3015.28 2482.19,3016.3 2844.38,3015.86 2884.38,3015.86 1549.11,3016.89 1772.31,3016.7 1785.93,3016.7 1799.54,3016.7 1813.15,3016.7 1826.76,3016.7 1840.38,3016.7 1853.99,3016.7 1867.6,3016.7 1881.21,3016.7 1894.83,3016.7 1908.44,3016.7 1922.05,3016.7 1935.66,3016.7 1949.28,3016.7 1962.89,3016.7 1976.5,3016.7 1990.11,3016.7 2003.73,3016.7 2017.34,3016.7 2030.95,3016.7 1428.72,3017.48 1468.72,3017.48 1628.72,3017.48 1668.72,3017.48 1708.72,3017.48 2068.72,3017.48 2108.72,3017.48 2282.72,3017.48 2308.72,3017.48 2348.72,3017.48 2388.72,3017.48 2414.72,3017.48 2575.47,3018.11 2601.47,3018.11 2641.47,3018.11 2681.47,3018.11 2722.67,3017.38 2922.67,3017.38 3028.72,3017.48 3068.72,3017.48 3108.72,3017.48 3148.72,3017.48 1608.22,3019.13 2261.35,3018.88 1504.25,3019.64 2171.24,3019.94 2451.18,3019.56 2495.22,3021.18 2797.3,3021.06 2997.3,3021.06 2216.24,3021.73 2539.1,3022.08 2737.63,3021.95 2768.35,3021.95 2937.63,3021.95 2968.35,3021.95 2156.41,3022.38 2202.33,3022.58 1594.34,3025.52 2247.26,3025.79 1518.34,3026.55 2981.06,3026.36 2781.06,3027.36 1563.42,3028.54 2438.62,3028.52 2508.77,3028.76 2555.02,3029.08 1772.31,3030.05 1785.93,3030.05 1799.54,3030.05 1813.15,3030.05 1826.76,3030.05 1840.38,3030.05 1853.99,3030.05 1867.6,3030.05 1881.21,3030.05 1894.83,3030.05 1908.44,3030.05 1922.05,3030.05 1935.66,3030.05 1949.28,3030.05 1962.89,3030.05 1976.5,3030.05 1990.11,3030.05 2003.73,3030.05 2484.89,3029.85 1549.11,3030.4 2017.45,3030.33 2030.15,3030.33 2725.38,3030.55 2923.11,3031.31 1612.59,3032.58 1695.45,3033.28 1708.15,3033.28 1720.86,3033.28 1733.56,3033.28 1746.26,3033.28 1758.97,3033.28 2261.35,3032.7 2453.87,3033.12 1504.25,3033.46 2172.32,3033.72 2497.24,3034.17 2937.63,3034.17 2968.35,3034.22 2159.4,3035.21 2737.63,3034.77 2768.35,3035.01 2216.24,3035.55 2542.33,3035.52 2203.01,3036.39 1598.08,3038.83 2247.26,3039.61 2982.5,3040.06 1518.34,3040.37 2781.55,3040.55 1566.22,3042.07 2512,3042.2 2559.23,3041.59 2442.03,3043.04 2489.21,3042.98 1549.11,3043.9 2017.45,3043.97 2030.15,3043.97 1619.61,3044.89 2725.38,3044.46 2923.33,3045.59 1504.25,3047.28 1695.46,3047.13 1708.16,3047.13 1720.86,3047.13 1733.56,3047.13 1746.26,3047.13 1759.3,3047.13 2261.35,3046.52 2457.58,3046.43 2501.58,3046.49 2937.37,3046.39 2968.53,3046.49 2158.24,3047.82 2172.33,3047.54 2737.63,3047.58 2768.35,3048.07 1632.12,3049.25 1644.69,3048.63 1657.36,3048.63 1670.06,3048.63 1682.76,3048.63 2547.32,3048.41 1606.07,3050.23 2202.98,3050.02 2216.24,3049.37 1518.34,3054.19 2247.26,3053.43 2565.37,3053.38 2781.47,3053.73 2982.64,3053.76 1571.37,3054.9 2516.54,3055.25 2494.36,3055.8 2804.38,3055.86 2844.38,3055.86 2884.38,3055.86 2446.35,3057.13 1428.72,3057.48 1468.72,3057.48 1549.22,3057.4 1617.02,3058.08 2017.45,3057.61 2030.15,3057.61 2068.72,3057.48 2108.72,3057.48 2282.72,3057.48 2308.72,3057.48 2348.72,3057.48 2388.72,3057.48 2414.72,3057.48 2601.47,3058.11 2641.47,3058.11 2681.47,3058.11 3002.72,3057.48 3028.72,3057.48 3068.72,3057.48 3108.72,3057.48 3148.72,3057.48 2725.38,3058.37 2937.37,3058.62 2968.61,3058.75 2462.03,3059.52 2923.11,3059.44 1504.25,3061.1 2158.84,3060.64 2261.35,3060.34 2553.89,3060.56 2737.63,3060.4 2768.35,3061.12 1628.75,3062.2 2172.33,3061.36 1642.51,3062.47 1656.28,3062.47 1670.04,3062.47 1683.8,3062.47 2216.24,3063.19 2203.01,3063.58 2573.42,3064.28 1562.53,3067.12 1578.71,3066.61 2247.26,3067.25 2781.33,3066.92 1518.34,3068.01 2500.48,3068.2 2522,3067.95 2982.08,3067.47 1549.37,3070.9 2017.45,3071.24 2030.15,3071.24 2451.82,3070.99 2936.26,3070.84 2967.59,3071.02 2158.73,3072.23 2467.77,3072.09 2561.96,3071.79 2921.88,3072.16 2724.21,3072.36 2737.35,3073.22 2261.35,3074.16 2767.99,3074.18 1504.4,3075.07 2172.33,3075.18 2582.96,3074.34 1589.1,3076.58 2216.24,3077.01 2203.05,3077.43 2508.02,3079.78 2529.22,3079.73 2781.26,3080.11 1564.44,3081.29 2247.26,3081.07 2980.22,3081.17 1518.63,3081.83 2571.4,3081.88 2594.24,3082.97 2965.44,3083.29 2917.46,3084.04 2932.72,3084.2 1549.97,3084.4 1601.17,3084.57 2017.45,3084.88 2030.49,3084.88 2043.19,3084.67 2055.9,3084.67 2068.6,3084.67 2081.31,3084.67 2458.14,3084.34 2473.94,3084.45 2721.79,3085.02 1578.24,3086.08 2156.92,3085.78 2734.89,3085.33 2766.48,3087.24 2261.35,3087.98 2170.16,3088.83 2607.91,3089.17 1505.15,3089.45 1614.9,3090.64 2201.39,3091.13 2216.02,3090.83 2516.29,3090.85 2537.41,3090.86 2582.17,3090.53 2622.96,3091.34 2710.56,3091.39 1590.6,3093.84 1629.29,3093.33 1644.69,3093.75 1657.73,3093.52 1670.77,3093.52 1683.8,3093.52 2637.56,3094.15 2652.16,3094.15 2778.88,3093.4 2247.26,3094.89 2666.76,3094.75 2681.36,3094.75 2695.96,3094.75 2976.59,3094.87 1519.8,3095.6 2149.56,3096.15 2481.52,3096.01 2727.89,3096.25 2804.38,3095.86 2844.38,3095.86 2884.38,3095.86 2911.82,3096.22 2465.53,3097.24 2927.05,3096.8 2961.43,3096.52 1428.72,3097.48 1468.72,3097.48 1552.04,3098.07 2282.72,3097.48 2308.72,3097.48 2348.72,3097.48 2388.72,3097.48 2428.72,3097.48 2594.07,3097.57 2995.72,3097.48 3028.72,3097.48 3068.72,3097.48 3108.72,3097.48 3148.72,3097.48 1603.88,3099.16 2017.45,3098.51 2030.49,3098.51 2043.19,3098.51 2055.89,3098.51 2068.59,3098.51 2081.29,3098.51 2093.99,3100.01 2107.89,3100.01 2122.12,3099.9 2136.25,3099.74 1565.81,3100.63 2163.59,3100.99 2525.4,3101.24 2261.35,3101.8 2546.41,3101.35 2606.84,3102.85 2716.57,3104.17 1507.45,3104.5 1617.08,3104.42 2197.17,3104.36 2216.02,3104.65 2620.28,3106.08 2773.48,3105.82 2902.61,3106.05 1630.7,3107.4 1644.69,3107.36 1657.36,3107.36 1670.06,3107.36 1682.76,3107.36 2489.44,3107.33 2634.04,3107.36 2647.86,3107.41 2661.68,3107.41 2675.5,3107.41 2689.32,3107.41 2703.14,3107.42 1522.87,3109.07 1695.46,3108.86 1708.16,3108.86 1720.86,3108.86 1733.56,3108.86 1746.26,3108.86 1759.3,3108.86 2247.26,3108.71 2919.42,3108.32 2955.7,3109.09 2971.14,3109.14 2152.72,3109.58 2473.82,3109.57 2756.1,3110.12 1556.24,3111.24 2535.42,3110.76 2556.91,3110.34 1573.34,3113.62 2092.95,3113.86 2107.89,3113.86 2122.83,3113.86 2137.77,3113.68 2890.96,3114.2 1596.8,3115.44 2190.12,3116.18 2203.41,3115.98 2261.35,3115.62 2766.92,3116.95 2498.55,3117.72 2216.02,3118.47 2568.67,3118.71 2910.01,3118.45 1511.65,3119.5 2546.24,3119.36 2747.64,3120 2482.93,3121.21 2949,3121.18 1527.46,3122.11 1695.45,3121.62 1708.15,3121.62 1720.86,3121.62 1733.56,3121.62 1746.26,3121.62 1759.3,3121.62 2879.35,3121.76 2247.26,3122.53 2963.97,3123.01 1562.75,3123.43 2580.34,3125.07 2181.7,3125.6 2784.01,3125.61 2797.83,3125.61 2811.65,3125.61 2825.47,3125.61 2839.24,3125.99 2867.16,3125.5 1581.95,3126.32 2558.02,3126.58 2853.14,3126.72 2899.09,3126.92 1617.45,3127.99 1643.45,3127.99 1669.45,3127.99 2197.07,3127.62 2507.92,3127.89 2737.41,3128.41 2756.79,3129.3 2770.79,3128.75 2261.35,3129.44 2216.02,3132.29 2492.75,3132.22 2940.26,3131.88 2570.41,3132.7 1517.45,3133.72 2171.18,3134.19 2886.9,3133.43 1533.44,3134.57 1571.24,3134.33 1592.37,3134.54 1695.45,3134.37 1708.15,3134.37 1720.86,3134.37 1733.56,3134.37 1746.26,3134.37 1759.3,3134.37 2611.26,3136 2721.82,3135.42 2955.11,3135.92 2247.26,3136.35 2518.32,3136.99 2582.33,3136.41 1428.72,3137.48 1468.72,3137.48 2282.72,3137.48 2308.72,3137.48 2348.72,3137.48 2388.72,3137.48 2428.72,3137.48 2468.72,3137.48 2638.9,3138.1 2666.54,3138.1 2694.18,3138.1 2873.7,3137.53 2988.72,3137.48 3028.72,3137.48 3068.72,3137.48 3108.72,3137.48 3148.72,3137.48 2203.8,3138.85 2159.1,3140.09 2599.74,3139.6 2625.08,3140.3 2652.72,3140.3 2680.36,3140.3 2708,3140.3 2733.34,3140.3 2748.31,3139.76 2763.28,3139.76 2777.1,3139.7 2790.92,3139.7 2804.74,3139.7 2818.56,3139.7 2832.38,3139.7 2846.2,3139.7 2860.02,3139.44 2184.22,3140.69 2930.58,3141.75 2261.35,3143.26 2503.3,3142.51 1581.34,3143.76 1603.73,3143.48 2146.11,3143.6 2092.95,3144.9 2105.99,3144.9 2119.03,3144.9 2132.85,3144.9 1540.79,3146.27 2216.02,3146.11 2529.28,3145.4 1524.79,3147.21 1617.21,3147.16 1695.46,3147.13 1708.16,3147.13 1720.86,3147.13 1733.56,3147.13 1746.26,3147.13 1759.3,3147.13 2944.91,3147.2 2172.33,3147.9 1630.84,3148.88 1644.69,3148.63 1657.36,3148.63 1670.06,3148.63 1682.76,3148.63 2247.26,3150.17 2919.89,3150.51 1592.8,3151.49 2514.88,3152.08 2203.8,3152.67 2541.07,3152.62 2160.28,3153.77 2189.99,3153.44 1549.7,3156.83 1605.33,3157.32 2147.32,3157.63 2261.35,3157.35 2907.92,3157.41 2933.22,3157.68 2093.99,3158.75 2106.69,3158.75 2119.39,3158.75 2133.34,3158.79 2553.54,3158.56 1533.89,3159.84 2017.45,3160.25 2030.49,3160.25 2043.19,3160.25 2055.89,3160.25 2068.59,3160.25 2081.29,3160.25 2216.02,3159.93 1618.62,3161.11 2527.21,3160.6 1632.37,3162.47 1644.69,3162.47 1657.73,3162.47 1670.77,3162.47 1683.8,3162.47 2247.26,3163.99 2566.38,3163.69 2895.45,3163.38 1559.81,3166.26 2579.77,3167.09 2920.47,3166.42 2540.59,3167.96 2882.23,3167.4 2593.36,3169.61 2868.62,3169.79 1544.57,3171.24 2176.35,3170.71 2200.9,3171.13 2607.14,3170.69 2620.96,3170.95 2634.78,3170.95 2648.6,3170.95 2662.42,3170.95 2676.24,3170.95 2690.06,3170.95 2703.88,3170.95 2717.7,3170.95 2731.52,3170.95 2745.34,3170.95 2759.16,3170.95 2772.98,3170.95 2786.8,3170.95 2800.62,3170.95 2814.18,3170.95 2827.74,3170.95 2841.3,3170.95 2854.86,3171.09 2259.02,3171.38 2017.45,3173 2030.49,3173 2043.19,3173 2055.9,3173 2068.6,3173 2081.31,3173 2216.04,3173.75 2554.31,3174.03 2906.77,3173.49 1570.88,3174.53 1428.72,3177.48 1468.72,3177.48 1508.72,3177.48 2246.73,3177.8 2282.72,3177.48 2308.72,3177.48 2348.72,3177.48 2388.72,3177.48 2428.72,3177.48 2468.72,3177.48 2508.72,3177.48 2948.72,3177.48 2988.72,3177.48 3028.72,3177.48 3068.72,3177.48 3108.72,3177.48 3148.72,3177.48 2568.73,3178.76 2892.11,3179.07 2103.91,3180.04 2129.91,3180.04 2155.91,3180.04 1556.32,3181.19 1582.77,3181.56 2583.55,3182.1 2877.31,3182.55 2598.41,3184.1 2199.62,3184.98 2613.36,3184.89 2627.73,3185.04 2641.69,3185.04 2655.51,3185.04 2669.33,3185.04 2683.15,3185.04 2696.97,3185.04 2710.79,3185.04 2724.61,3185.04 2738.43,3185.04 2752.25,3185.04 2766.07,3185.04 2779.89,3185.04 2793.71,3185.04 2807.53,3185.04 2821.35,3185.04 2835.17,3185.04 2848.99,3185.04 2862.71,3184.44 2017.45,3185.76 2030.49,3185.76 2043.19,3185.76 2055.9,3185.76 2068.6,3185.76 2081.31,3185.76 2258.62,3185.38 1595.54,3186.85 2213.25,3187.29 1569.02,3189.76 1608.87,3190.52 2244.32,3191.18 1621.34,3192.73 1633.81,3193.54 1646.3,3193.75 1658.8,3193.52 1671.3,3193.52 1683.8,3193.52 2189.02,3195.48 1582.88,3196.78 2017.45,3198.51 2030.49,3198.51 2043.19,3198.51 2055.89,3198.51 2068.59,3198.51 2081.29,3198.51 2206.36,3199.15 2255.92,3198.98 2093.99,3200.01 2106.69,3200.01 2119.39,3200.01 2133.3,3200.01 2147.02,3200.28 2161.16,3200.44 2175.52,3200.78 1597.64,3201.99 2239.42,3203.88 1612.69,3205.37 1627.83,3207.16 1642.76,3207.69 1657.36,3207.36 1670.06,3207.36 1682.76,3207.36 2195.82,3207.98 1695.46,3208.86 1708.16,3208.86 1720.86,3208.86 1733.56,3208.86 1746.26,3208.86 1758.97,3208.86 2250.82,3211.68 2183.42,3213.18 2092.95,3213.86 2105.76,3213.86 2118.56,3213.86 2131.37,3213.86 2144.18,3213.86 2156.98,3213.86 2169.79,3213.86 2232.02,3215.58 1428.72,3217.48 1468.72,3217.48 1508.72,3217.48 1548.72,3217.48 1588.72,3217.48 2268.72,3217.48 2308.72,3217.48 2348.72,3217.48 2388.72,3217.48 2428.72,3217.48 2468.72,3217.48 2508.72,3217.48 2548.72,3217.48 2588.72,3217.48 2628.72,3217.48 2668.72,3217.48 2708.72,3217.48 2748.72,3217.48 2788.72,3217.48 2828.72,3217.48 2868.72,3217.48 2908.72,3217.48 2948.72,3217.48 2988.72,3217.48 3028.72,3217.48 3068.72,3217.48 3108.72,3217.48 3148.72,3217.48 1628.72,3221.48 1668.72,3221.48 1695.45,3222.71 1708.15,3222.71 1720.86,3222.71 1733.56,3222.71 1746.26,3222.49 1758.97,3222.49 2243.62,3223.28 2222.62,3225.78 2234.22,3233.18 2212.12,3233.78 1746.26,3236.12 1759.62,3236.12 2200.23,3239.85 2223.35,3241.68 2187.42,3243.58 2092.95,3244.9 2105.45,3244.9 2117.95,3244.9 2132.02,3244.58 2146.18,3244.58 2160,3244.58 2173.81,3244.58 2211.12,3247.68 1746.26,3249.75 1759.62,3249.75 2198.12,3253.08 2184.94,3257.02 1428.72,3257.48 1468.72,3257.48 1508.72,3257.48 1548.72,3257.48 1588.72,3257.48 1628.72,3257.48 1668.72,3257.48 1708.72,3257.48 2145.1,3258.13 2157.91,3257.98 2228.72,3257.48 2268.72,3257.48 2308.72,3257.48 2348.72,3257.48 2388.72,3257.48 2428.72,3257.48 2468.72,3257.48 2508.72,3257.48 2548.72,3257.48 2588.72,3257.48 2628.72,3257.48 2668.72,3257.48 2708.72,3257.48 2748.72,3257.48 2788.72,3257.48 2828.72,3257.48 2868.72,3257.48 2908.72,3257.48 2948.72,3257.48 2988.72,3257.48 3028.72,3257.48 3068.72,3257.48 3108.72,3257.48 3148.72,3257.48 2093.99,3258.75 2106.69,3258.75 2119.5,3258.75 2132.3,3258.69 2170.71,3258.38 2017.78,3260.25 2030.49,3260.25 2043.19,3260.25 2055.89,3260.25 2068.59,3260.25 2081.29,3260.25 1746.26,3263.38 1759.62,3263.38 2017.78,3274.09 2030.49,3274.09 2043.19,3274.09 2055.9,3274.09 2068.6,3274.09 2081.31,3274.09 1746.26,3277.01 1759.88,3277.01 1773.49,3277.28 1787.1,3277.28 1800.72,3277.28 1814.33,3277.28 1827.94,3277.28 1841.55,3277.28 1855.17,3277.28 1868.78,3277.28 1882.39,3277.28 1896,3277.28 1909.62,3277.28 1923.23,3277.28 1936.84,3277.28 1950.45,3277.28 1964.07,3277.28 1977.68,3277.28 1991.29,3277.28 2004.9,3277.28 2018.25,3287.74 1746.26,3290.63 1759.88,3290.63 1773.49,3290.63 1787.1,3290.63 1800.72,3290.63 1814.33,3290.63 1827.94,3290.63 1841.55,3290.63 1855.17,3290.63 1868.78,3290.63 1882.39,3290.63 1896,3290.63 1909.62,3290.63 1923.23,3290.63 1936.84,3290.63 1950.45,3290.63 1964.07,3290.63 1977.68,3290.63 1991.29,3290.63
